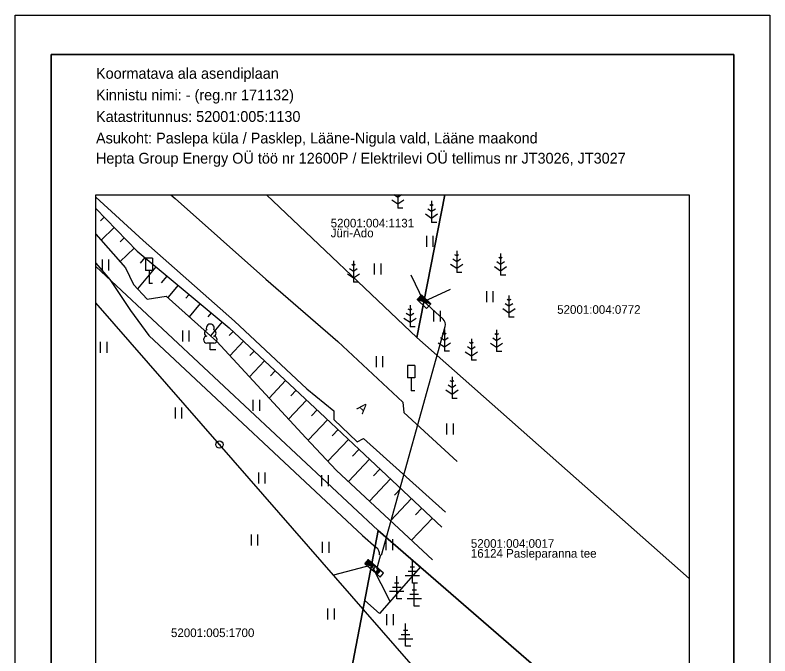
# Model space of a CAD drawing. Extents: x 469357.8 to 469410.3, y 6542153.5 to 6542227.7.
# Drawn here: x 469357.8 to 469410.3, y 6542183.1 to 6542227.7 of the extents above; entities that cross this region are included whole.
import ezdxf

# ---------------------------------------------------------------- set-up
doc = ezdxf.new("R2010")
doc.units = 0
for name, color, linetype in [('HALJASTUS', 7, 'Continuous'), ('Hepta_tarbijatoru', 7, 'Continuous'), ('KASUTUSALA', 7, 'Continuous'), ('KPOHULIIN', 7, 'Continuous'), ('LIIKLUS', 7, 'Continuous'), ('MADALPINGE', 7, 'Continuous'), ('PIIR', 7, 'Continuous'), ('POST', 7, 'Continuous'), ('PUU', 7, 'Continuous'), ('RELJEEF', 7, 'Continuous'), ('TEE', 7, 'Continuous'), ('VORMISTUS', 7, 'Continuous')]:
    doc.layers.add(name, color=color, linetype=linetype)

msp = doc.modelspace()

# ---------------------------------------------------------------- linework, layer by layer
at = {"layer": 'HALJASTUS'}
for p, q in [((469386.366, 6542212.352), (469386.366, 6542211.591)), ((469386.821, 6542212.352), (469386.821, 6542211.591)), ((469363.813, 6542210.709), (469363.813, 6542209.948)), ((469364.268, 6542210.709), (469364.268, 6542209.948)), ((469382.742, 6542210.432), (469382.742, 6542209.671)), ((469383.197, 6542210.432), (469383.197, 6542209.671)), ((469390.544, 6542208.512), (469390.544, 6542207.751)), ((469390.999, 6542208.512), (469390.999, 6542207.751)), ((469386.863, 6542207.147), (469386.863, 6542206.386)), ((469387.318, 6542207.147), (469387.318, 6542206.386)), ((469369.398, 6542205.761), (469369.398, 6542205)), ((469369.853, 6542205.761), (469369.853, 6542205)), ((469363.685, 6542204.972), (469363.685, 6542204.211)), ((469364.14, 6542204.972), (469364.14, 6542204.211)), ((469382.87, 6542203.99), (469382.87, 6542203.229)), ((469383.325, 6542203.99), (469383.325, 6542203.229)), ((469374.301, 6542200.94), (469374.301, 6542200.179)), ((469374.756, 6542200.94), (469374.756, 6542200.179)), ((469368.886, 6542200.407), (469368.886, 6542199.646)), ((469369.341, 6542200.407), (469369.341, 6542199.646)), ((469387.773, 6542199.298), (469387.773, 6542198.537)), ((469388.228, 6542199.298), (469388.228, 6542198.537)), ((469374.685, 6542195.885), (469374.685, 6542195.124)), ((469375.14, 6542195.885), (469375.14, 6542195.124)), ((469379.076, 6542195.693), (469379.076, 6542194.932)), ((469379.531, 6542195.693), (469379.531, 6542194.932)), ((469374.173, 6542191.577), (469374.173, 6542190.815)), ((469374.628, 6542191.577), (469374.628, 6542190.815)), ((469379.118, 6542191.065), (469379.118, 6542190.304)), ((469379.573, 6542191.065), (469379.573, 6542190.304)), ((469383.552, 6542191.257), (469383.552, 6542190.495)), ((469384.007, 6542191.257), (469384.007, 6542190.495)), ((469379.502, 6542186.415), (469379.502, 6542185.654)), ((469379.957, 6542186.415), (469379.957, 6542185.654)), ((469383.595, 6542186.031), (469383.595, 6542185.27)), ((469384.05, 6542186.031), (469384.05, 6542185.27))]:
    msp.add_line(p, q, dxfattribs=at)
at = {"layer": 'Hepta_tarbijatoru'}
for points in [[(469386.196, 6542207.779), (469385.314, 6542209.631)], [(469386.196, 6542207.779), (469388.057, 6542208.638)], [(469382.553, 6542189.429), (469379.901, 6542188.753)], [(469382.553, 6542189.429), (469383.86, 6542186.881)]]:
    msp.add_lwpolyline(points, dxfattribs=at)
at = {"layer": 'KASUTUSALA'}
msp.add_lwpolyline([(469385.95, 6542189.315), (469383.106, 6542186.083), (469382.083, 6542186.983), (469383.02, 6542191.86), (469384.421, 6542190.643)], close=True, dxfattribs=at)
at = {"layer": 'KPOHULIIN'}
msp.add_lwpolyline([(469402.605, 6542162.721), (469371.981, 6542197.833), (469363.387, 6542207.705)], dxfattribs=at)
at = {"layer": 'LIIKLUS'}
for p, q in [((469366.826, 6542210.794), (469366.826, 6542209.944)), ((469367.326, 6542210.794), (469366.826, 6542210.794)), ((469367.326, 6542210.794), (469367.326, 6542209.944)), ((469367.326, 6542209.944), (469366.826, 6542209.944)), ((469367.076, 6542209.944), (469367.076, 6542209.044)), ((469367.326, 6542209.044), (469367.076, 6542209.044)), ((469385.055, 6542203.325), (469385.055, 6542202.475)), ((469385.555, 6542203.325), (469385.055, 6542203.325)), ((469385.555, 6542203.325), (469385.555, 6542202.475)), ((469385.555, 6542202.475), (469385.055, 6542202.475)), ((469385.305, 6542202.475), (469385.305, 6542201.575)), ((469385.555, 6542201.575), (469385.305, 6542201.575))]:
    msp.add_line(p, q, dxfattribs=at)
at = {"layer": 'MADALPINGE'}
for p, q in [((469386.024, 6542208.25), (469385.716, 6542207.924)), ((469386.623, 6542207.65), (469386.007, 6542208.232)), ((469386.65, 6542207.642), (469386.016, 6542208.241)), ((469386.677, 6542207.633), (469386.024, 6542208.25)), ((469385.716, 6542207.924), (469386.369, 6542207.307)), ((469385.716, 6542207.924), (469386.677, 6542207.633)), ((469385.727, 6542207.921), (469385.72, 6542207.928)), ((469385.754, 6542207.913), (469385.728, 6542207.937)), ((469385.781, 6542207.904), (469385.737, 6542207.946)), ((469385.808, 6542207.896), (469385.746, 6542207.955)), ((469385.836, 6542207.888), (469385.754, 6542207.965)), ((469385.863, 6542207.88), (469385.763, 6542207.974)), ((469385.89, 6542207.872), (469385.772, 6542207.983)), ((469385.917, 6542207.863), (469385.781, 6542207.992)), ((469385.944, 6542207.855), (469385.789, 6542208.001)), ((469385.971, 6542207.847), (469385.798, 6542208.011)), ((469385.998, 6542207.839), (469385.807, 6542208.02)), ((469386.026, 6542207.83), (469385.815, 6542208.029)), ((469386.053, 6542207.822), (469385.824, 6542208.038)), ((469386.08, 6542207.814), (469385.833, 6542208.047)), ((469386.107, 6542207.806), (469385.841, 6542208.057)), ((469386.134, 6542207.798), (469385.85, 6542208.066)), ((469386.161, 6542207.789), (469385.859, 6542208.075)), ((469386.188, 6542207.781), (469385.868, 6542208.084)), ((469386.216, 6542207.773), (469385.876, 6542208.094)), ((469386.243, 6542207.765), (469385.885, 6542208.103)), ((469386.27, 6542207.757), (469385.894, 6542208.112)), ((469386.297, 6542207.748), (469385.902, 6542208.121)), ((469386.324, 6542207.74), (469385.911, 6542208.13)), ((469386.351, 6542207.732), (469385.92, 6542208.14)), ((469386.378, 6542207.724), (469385.928, 6542208.149)), ((469386.405, 6542207.716), (469385.937, 6542208.158)), ((469386.433, 6542207.707), (469385.946, 6542208.167)), ((469386.46, 6542207.699), (469385.955, 6542208.176)), ((469386.487, 6542207.691), (469385.963, 6542208.186)), ((469386.514, 6542207.683), (469385.972, 6542208.195)), ((469386.541, 6542207.675), (469385.981, 6542208.204)), ((469386.568, 6542207.666), (469385.989, 6542208.213)), ((469386.595, 6542207.658), (469385.998, 6542208.223)), ((469386.369, 6542207.307), (469386.677, 6542207.633)), ((469382.317, 6542189.829), (469382.081, 6542189.561)), ((469382.081, 6542189.561), (469382.619, 6542189.087)), ((469382.081, 6542189.561), (469382.855, 6542189.356)), ((469382.089, 6542189.558), (469382.083, 6542189.564)), ((469382.111, 6542189.552), (469382.09, 6542189.571)), ((469382.133, 6542189.547), (469382.097, 6542189.579)), ((469382.155, 6542189.541), (469382.103, 6542189.586)), ((469382.177, 6542189.535), (469382.11, 6542189.594)), ((469382.199, 6542189.529), (469382.117, 6542189.602)), ((469382.221, 6542189.524), (469382.123, 6542189.609)), ((469382.243, 6542189.518), (469382.13, 6542189.617)), ((469382.264, 6542189.512), (469382.137, 6542189.624)), ((469382.286, 6542189.506), (469382.143, 6542189.632)), ((469382.308, 6542189.5), (469382.15, 6542189.64)), ((469382.33, 6542189.495), (469382.157, 6542189.647)), ((469382.352, 6542189.489), (469382.163, 6542189.655)), ((469382.374, 6542189.483), (469382.17, 6542189.662)), ((469382.396, 6542189.477), (469382.177, 6542189.67)), ((469382.418, 6542189.471), (469382.184, 6542189.678)), ((469382.439, 6542189.466), (469382.19, 6542189.685)), ((469382.461, 6542189.46), (469382.197, 6542189.693)), ((469382.483, 6542189.454), (469382.204, 6542189.7)), ((469382.505, 6542189.448), (469382.21, 6542189.708)), ((469382.527, 6542189.443), (469382.217, 6542189.715)), ((469382.549, 6542189.437), (469382.224, 6542189.723)), ((469382.571, 6542189.431), (469382.23, 6542189.731)), ((469382.593, 6542189.425), (469382.237, 6542189.738)), ((469382.615, 6542189.419), (469382.244, 6542189.746)), ((469382.636, 6542189.414), (469382.25, 6542189.753)), ((469382.658, 6542189.408), (469382.257, 6542189.761)), ((469382.68, 6542189.402), (469382.264, 6542189.769)), ((469382.702, 6542189.396), (469382.27, 6542189.776)), ((469382.724, 6542189.39), (469382.277, 6542189.784)), ((469382.746, 6542189.385), (469382.284, 6542189.791)), ((469382.768, 6542189.379), (469382.29, 6542189.799)), ((469382.79, 6542189.373), (469382.297, 6542189.807)), ((469382.811, 6542189.367), (469382.304, 6542189.814)), ((469382.833, 6542189.362), (469382.311, 6542189.822)), ((469382.855, 6542189.356), (469382.317, 6542189.829)), ((469382.855, 6542189.356), (469382.619, 6542189.087)), ((469382.619, 6542189.087), (469382.855, 6542189.356)), ((469383.393, 6542188.882), (469382.855, 6542189.356)), ((469382.619, 6542189.087), (469383.157, 6542188.613)), ((469382.826, 6542188.904), (469383.063, 6542189.173)), ((469382.832, 6542188.911), (469382.955, 6542188.803)), ((469382.838, 6542188.917), (469382.961, 6542188.81)), ((469382.844, 6542188.924), (469382.967, 6542188.817)), ((469382.847, 6542188.927), (469382.969, 6542188.82)), ((469382.853, 6542188.934), (469382.975, 6542188.826)), ((469382.859, 6542188.941), (469382.981, 6542188.833)), ((469382.865, 6542188.948), (469382.987, 6542188.84)), ((469382.871, 6542188.954), (469382.993, 6542188.847)), ((469382.877, 6542188.961), (469382.999, 6542188.853)), ((469382.883, 6542188.968), (469383.005, 6542188.86)), ((469382.889, 6542188.975), (469383.011, 6542188.867)), ((469382.895, 6542188.981), (469383.017, 6542188.874)), ((469382.9, 6542188.988), (469383.023, 6542188.88)), ((469382.905, 6542188.993), (469383.027, 6542188.886)), ((469382.911, 6542189), (469383.033, 6542188.893)), ((469382.917, 6542189.007), (469383.039, 6542188.899)), ((469382.923, 6542189.014), (469383.045, 6542188.906)), ((469382.928, 6542189.019), (469383.05, 6542188.911)), ((469382.934, 6542189.026), (469383.056, 6542188.918)), ((469382.94, 6542189.033), (469383.062, 6542188.925)), ((469382.946, 6542189.039), (469383.068, 6542188.932)), ((469382.949, 6542188.796), (469383.185, 6542189.065)), ((469382.95, 6542189.045), (469383.073, 6542188.937)), ((469382.956, 6542189.051), (469383.079, 6542188.944)), ((469382.962, 6542189.058), (469383.084, 6542188.951)), ((469382.968, 6542189.065), (469383.09, 6542188.957)), ((469382.973, 6542189.07), (469383.095, 6542188.963)), ((469382.979, 6542189.077), (469383.101, 6542188.969)), ((469382.985, 6542189.084), (469383.107, 6542188.976)), ((469382.991, 6542189.091), (469383.113, 6542188.983)), ((469382.995, 6542189.096), (469383.118, 6542188.988)), ((469383.001, 6542189.103), (469383.124, 6542188.995)), ((469383.007, 6542189.109), (469383.13, 6542189.002)), ((469383.013, 6542189.116), (469383.135, 6542189.009)), ((469383.018, 6542189.122), (469383.14, 6542189.014)), ((469383.024, 6542189.128), (469383.146, 6542189.021)), ((469383.03, 6542189.135), (469383.152, 6542189.027)), ((469383.036, 6542189.142), (469383.158, 6542189.034)), ((469383.04, 6542189.147), (469383.163, 6542189.04)), ((469383.046, 6542189.154), (469383.169, 6542189.046)), ((469383.052, 6542189.161), (469383.175, 6542189.053)), ((469383.058, 6542189.167), (469383.181, 6542189.06)), ((469383.157, 6542188.613), (469383.393, 6542188.882))]:
    msp.add_line(p, q, dxfattribs=at)
for points in [[(469363.387, 6542210.448), (469364.355, 6542209.323), (469365.778, 6542207.155), (469367.055, 6542205.427), (469381.934, 6542191.507), (469382.877, 6542190.671)], [(469387.528, 6542206.562), (469386.196, 6542207.779)], [(469383.245, 6542190.144), (469387.673, 6542206.059)], [(469383.18, 6542190.157), (469382.891, 6542189.131)]]:
    msp.add_lwpolyline(points, dxfattribs=at)
for centre, radius, start, end in [((469387.191, 6542206.193), 0.5, 344.4513, 47.5946), ((469382.501, 6542190.198), 0.605, 356.4922, 51.474)]:
    msp.add_arc(centre, radius, start, end, dxfattribs=at)
at = {"layer": 'PIIR'}
for points in [[(469375.245, 6542215.221), (469385.71, 6542205.29), (469387.651, 6542215.221)], [(469404.637, 6542188.501), (469385.71, 6542205.29), (469375.245, 6542215.221)], [(469387.651, 6542215.221), (469385.71, 6542205.29), (469404.637, 6542188.501)], [(469363.387, 6542210.229), (469383.02, 6542191.86), (469404.637, 6542173.084)], [(469377.423, 6542162.721), (469383.02, 6542191.86), (469363.387, 6542210.229)], [(469404.637, 6542173.084), (469383.02, 6542191.86), (469377.423, 6542162.721)]]:
    msp.add_lwpolyline(points, dxfattribs=at)
at = {"layer": 'POST'}
for radius in [0.25, 0.0234]:
    msp.add_circle((469371.981, 6542197.833), radius, dxfattribs=at)
at = {"layer": 'PUU'}
for p, q in [((469384.38, 6542215.027), (469384.113, 6542215.205)), ((469384.38, 6542215.221), (469384.38, 6542214.277)), ((469384.647, 6542215.205), (469384.38, 6542215.027)), ((469383.956, 6542214.866), (469384.38, 6542214.583)), ((469384.38, 6542214.583), (469384.804, 6542214.866)), ((469386.726, 6542214.443), (469386.602, 6542214.526)), ((469386.726, 6542214.793), (469386.726, 6542213.293)), ((469386.851, 6542214.526), (469386.726, 6542214.443)), ((469384.74, 6542214.277), (469384.38, 6542214.277)), ((469386.726, 6542214.043), (469386.46, 6542214.221)), ((469386.993, 6542214.221), (469386.726, 6542214.043)), ((469386.302, 6542213.882), (469386.726, 6542213.599)), ((469386.726, 6542213.599), (469387.151, 6542213.882)), ((469387.086, 6542213.293), (469386.726, 6542213.293)), ((469388.476, 6542210.958), (469388.351, 6542211.041)), ((469388.476, 6542211.308), (469388.476, 6542209.808)), ((469388.6, 6542211.041), (469388.476, 6542210.958)), ((469391.527, 6542210.775), (469391.402, 6542210.858)), ((469391.527, 6542211.125), (469391.527, 6542209.625)), ((469391.651, 6542210.858), (469391.527, 6542210.775)), ((469381.297, 6542210.278), (469381.173, 6542210.361)), ((469381.297, 6542210.628), (469381.297, 6542209.128)), ((469381.422, 6542210.361), (469381.297, 6542210.278)), ((469388.051, 6542210.398), (469388.476, 6542210.115)), ((469388.476, 6542210.558), (469388.209, 6542210.736)), ((469388.742, 6542210.736), (469388.476, 6542210.558)), ((469388.476, 6542210.115), (469388.9, 6542210.398)), ((469391.527, 6542210.375), (469391.26, 6542210.552)), ((469391.793, 6542210.552), (469391.527, 6542210.375)), ((469381.297, 6542209.878), (469381.031, 6542210.056)), ((469381.564, 6542210.056), (469381.297, 6542209.878)), ((469388.836, 6542209.808), (469388.476, 6542209.808)), ((469391.103, 6542210.214), (469391.527, 6542209.931)), ((469391.527, 6542209.931), (469391.951, 6542210.214)), ((469380.873, 6542209.718), (469381.297, 6542209.435)), ((469381.297, 6542209.435), (469381.722, 6542209.718)), ((469391.887, 6542209.625), (469391.527, 6542209.625)), ((469381.657, 6542209.128), (469381.297, 6542209.128)), ((469392.111, 6542207.853), (469391.987, 6542207.936)), ((469392.111, 6542208.203), (469392.111, 6542206.703)), ((469392.236, 6542207.936), (469392.111, 6542207.853)), ((469385.232, 6542207.184), (469385.107, 6542207.267)), ((469385.232, 6542207.534), (469385.232, 6542206.034)), ((469385.356, 6542207.267), (469385.232, 6542207.184)), ((469391.687, 6542207.293), (469392.111, 6542207.01)), ((469392.111, 6542207.453), (469391.845, 6542207.631)), ((469392.378, 6542207.631), (469392.111, 6542207.453)), ((469392.111, 6542207.01), (469392.535, 6542207.293)), ((469385.232, 6542206.784), (469384.965, 6542206.962)), ((469385.498, 6542206.962), (469385.232, 6542206.784)), ((469392.471, 6542206.703), (469392.111, 6542206.703)), ((469384.807, 6542206.623), (469385.232, 6542206.34)), ((469385.232, 6542206.34), (469385.656, 6542206.623)), ((469385.592, 6542206.034), (469385.232, 6542206.034)), ((469387.62, 6542205.834), (469387.62, 6542204.334)), ((469391.249, 6542205.808), (469391.249, 6542204.308)), ((469387.62, 6542205.084), (469387.354, 6542205.262)), ((469387.62, 6542205.484), (469387.496, 6542205.567)), ((469387.745, 6542205.567), (469387.62, 6542205.484)), ((469387.887, 6542205.262), (469387.62, 6542205.084)), ((469389.497, 6542205.201), (469389.497, 6542203.701)), ((469391.249, 6542205.058), (469390.982, 6542205.236)), ((469391.249, 6542205.458), (469391.124, 6542205.541)), ((469391.373, 6542205.541), (469391.249, 6542205.458)), ((469391.515, 6542205.236), (469391.249, 6542205.058)), ((469371.576, 6542204.895), (469371.096, 6542204.895)), ((469371.336, 6542204.42), (469371.336, 6542204.895)), ((469387.196, 6542204.923), (469387.62, 6542204.641)), ((469387.62, 6542204.641), (469388.045, 6542204.923)), ((469389.497, 6542204.451), (469389.23, 6542204.628)), ((469389.497, 6542204.851), (469389.372, 6542204.934)), ((469389.621, 6542204.934), (469389.497, 6542204.851)), ((469389.763, 6542204.628), (469389.497, 6542204.451)), ((469390.824, 6542204.898), (469391.249, 6542204.615)), ((469391.249, 6542204.615), (469391.673, 6542204.898)), ((469371.716, 6542204.42), (469371.336, 6542204.42)), ((469387.98, 6542204.334), (469387.62, 6542204.334)), ((469389.072, 6542204.29), (469389.497, 6542204.007)), ((469389.497, 6542204.007), (469389.921, 6542204.29)), ((469391.609, 6542204.308), (469391.249, 6542204.308)), ((469389.857, 6542203.701), (469389.497, 6542203.701)), ((469388.153, 6542202.542), (469388.153, 6542201.042)), ((469388.153, 6542201.792), (469387.886, 6542201.969)), ((469388.153, 6542202.192), (469388.029, 6542202.275)), ((469388.278, 6542202.275), (469388.153, 6542202.192)), ((469388.42, 6542201.969), (469388.153, 6542201.792)), ((469387.729, 6542201.631), (469388.153, 6542201.348)), ((469388.153, 6542201.348), (469388.577, 6542201.631)), ((469388.513, 6542201.042), (469388.153, 6542201.042)), ((469385.395, 6542188.194), (469385.395, 6542189.769)), ((469385.695, 6542188.994), (469385.095, 6542188.994)), ((469385.545, 6542189.294), (469385.245, 6542189.294)), ((469384.308, 6542187.096), (469384.308, 6542188.671)), ((469385.895, 6542188.694), (469384.895, 6542188.694)), ((469384.608, 6542187.896), (469384.008, 6542187.896)), ((469384.458, 6542188.196), (469384.158, 6542188.196)), ((469385.755, 6542188.194), (469385.395, 6542188.194)), ((469385.525, 6542186.591), (469385.525, 6542188.166)), ((469384.808, 6542187.596), (469383.808, 6542187.596)), ((469385.825, 6542187.391), (469385.225, 6542187.391)), ((469385.675, 6542187.691), (469385.375, 6542187.691)), ((469384.668, 6542187.096), (469384.308, 6542187.096)), ((469386.025, 6542187.091), (469385.025, 6542187.091)), ((469385.885, 6542186.591), (469385.525, 6542186.591)), ((469384.92, 6542183.801), (469384.92, 6542185.376)), ((469385.22, 6542184.601), (469384.62, 6542184.601)), ((469385.07, 6542184.901), (469384.77, 6542184.901)), ((469385.42, 6542184.301), (469384.42, 6542184.301)), ((469385.28, 6542183.801), (469384.92, 6542183.801))]:
    msp.add_line(p, q, dxfattribs=at)
for centre, radius, start, end in [((469371.336, 6542205.94), 0.277, 332.5799, 207.4201), ((469371.166, 6542205.592), 0.233, 109.0217, 253.1415), ((469371.506, 6542205.592), 0.233, 286.8508, 70.9859), ((469371.098, 6542205.132), 0.238, 90.0016, 269.3953), ((469371.573, 6542205.132), 0.238, 270.6047, 89.9984)]:
    msp.add_arc(centre, radius, start, end, dxfattribs=at)
at = {"layer": 'RELJEEF'}
for p, q in [((469363.961, 6542213.666), (469363.697, 6542213.412)), ((469364.655, 6542212.947), (469363.743, 6542212.067)), ((469365.349, 6542212.227), (469365.066, 6542211.953)), ((469366.044, 6542211.507), (469365.064, 6542210.562)), ((469366.789, 6542210.843), (469366.467, 6542210.456)), ((469367.558, 6542210.203), (469366.277, 6542208.665)), ((469368.326, 6542209.563), (469367.923, 6542209.079)), ((469369.095, 6542208.923), (469368.375, 6542208.059)), ((469369.863, 6542208.283), (469369.641, 6542208.016)), ((469370.632, 6542207.644), (469369.867, 6542206.725)), ((469371.4, 6542207.004), (469371.164, 6542206.72)), ((469372.169, 6542206.364), (469371.358, 6542205.39)), ((469372.923, 6542205.708), (469372.654, 6542205.42)), ((469373.653, 6542205.025), (469372.706, 6542204.013)), ((469374.384, 6542204.342), (469374.085, 6542204.022)), ((469375.114, 6542203.659), (469374.067, 6542202.54)), ((469375.844, 6542202.975), (469375.515, 6542202.624)), ((469376.574, 6542202.292), (469375.428, 6542201.067)), ((469377.305, 6542201.609), (469376.946, 6542201.225)), ((469378.035, 6542200.926), (469376.789, 6542199.594)), ((469378.765, 6542200.243), (469378.376, 6542199.827)), ((469379.494, 6542199.559), (469378.145, 6542198.13)), ((469380.221, 6542198.872), (469379.805, 6542198.43)), ((469380.949, 6542198.185), (469379.519, 6542196.671)), ((469381.676, 6542197.499), (469381.236, 6542197.033)), ((469382.406, 6542196.816), (469380.949, 6542195.259)), ((469383.136, 6542196.132), (469382.7, 6542195.666)), ((469383.866, 6542195.449), (469382.413, 6542193.895)), ((469384.597, 6542194.766), (469384.161, 6542194.3)), ((469385.327, 6542194.083), (469383.876, 6542192.532)), ((469386.057, 6542193.4), (469385.622, 6542192.935)), ((469386.788, 6542192.717), (469385.339, 6542191.169))]:
    msp.add_line(p, q, dxfattribs=at)
for points in [[(469363.387, 6542214.261), (469366.257, 6542211.286), (469372.659, 6542205.955), (469379.321, 6542199.722), (469381.683, 6542197.492), (469387.454, 6542192.094)], [(469363.387, 6542212.473), (469365.449, 6542210.123), (469365.99, 6542208.972), (469366.955, 6542207.944), (469368.26, 6542208.163), (469371.794, 6542205), (469377.984, 6542198.301), (469380.124, 6542196.027), (469386.793, 6542189.814)]]:
    msp.add_lwpolyline(points, dxfattribs=at)
at = {"layer": 'TEE'}
for points in [[(469363.387, 6542215.054), (469366.662, 6542212.035), (469373.024, 6542206.414), (469378.054, 6542201.72), (469379.935, 6542200.169), (469379.92, 6542199.582), (469381.553, 6542198.02), (469381.998, 6542198.266), (469387.691, 6542193.138)], [(469368.603, 6542215.221), (469368.893, 6542214.948), (469375.209, 6542209.343), (469380.212, 6542205.014), (469384.737, 6542200.792), (469384.795, 6542200.073), (469388.511, 6542196.655)]]:
    msp.add_lwpolyline(points, dxfattribs=at)
at = {"layer": 'VORMISTUS'}
for points in [[(469357.762, 6542227.721), (469410.262, 6542227.721), (469410.262, 6542153.471), (469357.762, 6542153.471)], [(469360.262, 6542156.221), (469407.762, 6542156.221), (469407.762, 6542224.971), (469360.262, 6542224.971)], [(469360.262, 6542224.971), (469407.762, 6542224.971), (469407.762, 6542156.221), (469360.262, 6542156.221)], [(469404.637, 6542162.721), (469363.387, 6542162.721), (469363.387, 6542215.221), (469404.637, 6542215.221)]]:
    msp.add_lwpolyline(points, close=True, dxfattribs=at)

# ---------------------------------------------------------------- texts
at = {"layer": 'PIIR'}
for s, p in [('52001:004:1131', (469379.712, 6542212.944)), ('Jüri-Ado', (469379.712, 6542212.257)), ('52001:004:0772', (469395.464, 6542206.931)), ('52001:004:0017', (469389.462, 6542190.649)), ('16124 Pasleparanna tee', (469389.462, 6542189.963)), ('52001:005:1700', (469368.604, 6542184.434))]:
    msp.add_text(s, height=0.6, dxfattribs=at).set_placement(p)
at = {"layer": 'TEE'}
msp.add_text('A', height=0.7, rotation=318.1415, dxfattribs=at).set_placement((469381.471, 6542200.332))
at = {"layer": 'VORMISTUS'}
for s, p in [('Koormatava ala asendiplaan', (469363.389, 6542223.289)), ('Kinnistu nimi: - (reg.nr 171132)', (469363.389, 6542221.789)), ('Katastritunnus: 52001:005:1130', (469363.389, 6542220.289)), ('Asukoht: Paslepa küla / Pasklep, Lääne-Nigula vald, Lääne maakond', (469363.389, 6542218.789))]:
    msp.add_text(s, height=0.75, dxfattribs=at).set_placement(p)
msp.add_text('Hepta Group Energy OÜ töö nr 12600P / Elektrilevi OÜ tellimus nr JT3026, JT3027', height=0.75, rotation=360, dxfattribs=at).set_placement((469363.386, 6542217.386))

doc.saveas('drawing.dxf')
